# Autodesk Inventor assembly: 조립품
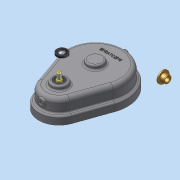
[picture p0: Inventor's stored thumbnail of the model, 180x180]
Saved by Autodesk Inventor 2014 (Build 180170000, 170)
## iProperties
Created: 2024-05
Part Number: 조립품
Document SubType Name: Assembly
Designer: dg
Author: dg
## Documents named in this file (9)
- C:\Users\dg\Desktop\740504V1007\조립품.iam
- C:\Users\dg\Desktop\740504V1007\본체.ipt
- C:\Users\dg\Desktop\740504V1007\가져온 구성요소\오일리스 부시\오일리스 부시.ipt
- C:\Users\dg\Desktop\740504V1007\가져온 구성요소\하단 축\하단 축.ipt
- C:\Users\dg\Desktop\740504V1007\가져온 구성요소\오일 실 10 20 4\오일 실 10 20 4.ipt
- C:\Users\dg\Desktop\740504V1007\가져온 구성요소\평행키 5x5x12\평행키 5x5x12.ipt
- C:\Users\dg\Desktop\740504V1007\가져온 구성요소\상단 축\상단 축.ipt
- C:\Users\dg\Desktop\740504V1007\가져온 구성요소\스퍼기어A\스퍼기어A.ipt
- C:\Users\dg\Desktop\740504V1007\가져온 구성요소\스퍼기어B\스퍼기어B.ipt
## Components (1 placed, 1 different names)
1. 하단 축:1
